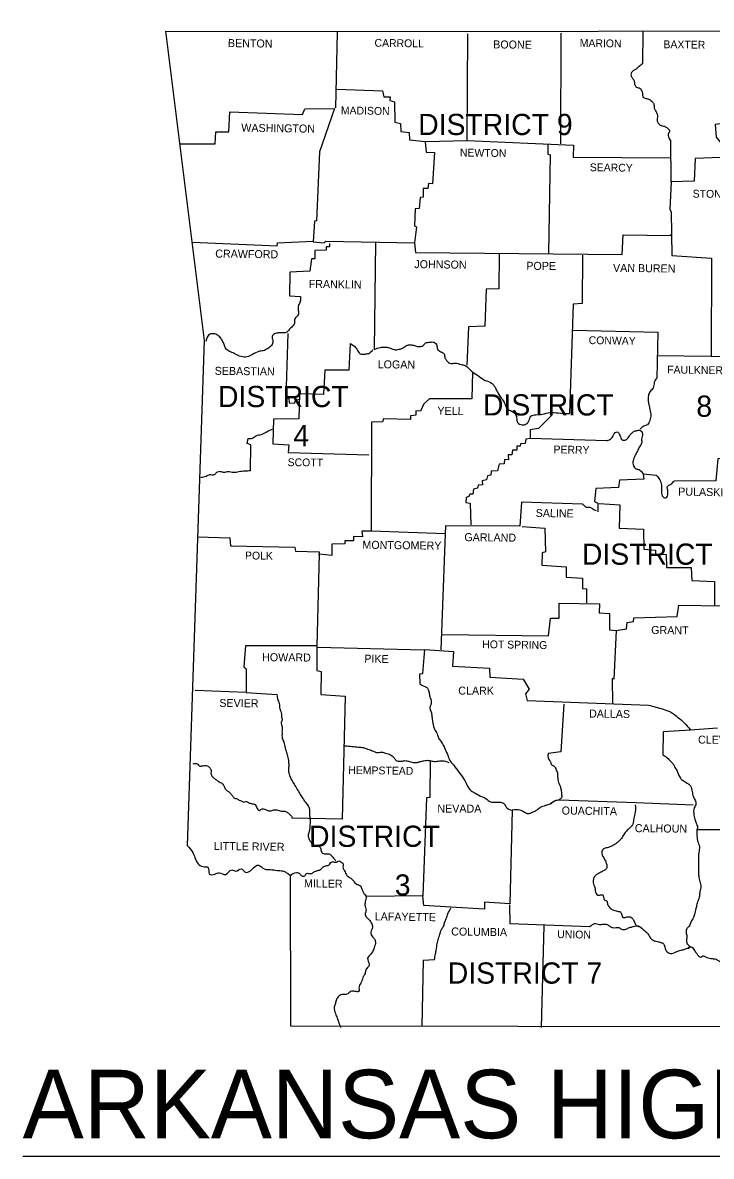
# Model space of a CAD drawing. Extents: x -42408 to 34530, y -43140 to 20491.
# Drawn here: x 7249 to 9102, y 6993 to 10043 of the extents above; entities that cross this region are included whole.
import ezdxf

# ---------------------------------------------------------------- set-up
doc = ezdxf.new("R2010")
doc.units = 0
for name, color, linetype in [('1', 7, 'Continuous'), ('2', 7, 'Continuous'), ('3', 7, 'Continuous')]:
    doc.layers.add(name, color=color, linetype=linetype)

msp = doc.modelspace()

# ---------------------------------------------------------------- linework, layer by layer
at = {"layer": '1'}
for points in [[(7633.7, 10020), (8443.3, 10019.5), (9153.8, 10021), (9991.9, 10034), (10380.4, 10043)], [(7633.7, 10020), (7737.4, 9187.8), (7692.3, 7829.5)], [(8095.9, 10017), (8091.3, 9814.2)], [(8094.9, 9863.7), (8218, 9859.7), (8221, 9843.7), (8238, 9843.2), (8237.5, 9833.2), (8249.6, 9830.2), (8250.6, 9775.6), (8266.1, 9772.1), (8267.1, 9750.6), (8289.1, 9747.6), (8290.1, 9727.6), (8333.7, 9723.1), (8445.8, 9725.6), (8446.8, 10013.4)], [(8697.7, 10014.5), (8696.2, 9717.1)], [(8918, 10018), (8917, 9932.3)], [(9153.8, 10018), (9154.8, 9898.8), (9146.3, 9898.3), (9147.8, 9773.6), (9112.7, 9768.6), (9115.7, 9735.1), (9127.7, 9719.6), (9126.7, 9680), (9058.6, 9677.5), (9056.1, 9616.4), (8994.1, 9614.4), (8991, 9540.3), (8994.6, 9534.3), (8996.1, 9416.2), (9103.2, 9409.1), (9101.7, 9145.3), (9186.8, 9142.8), (9186.8, 8874.4), (9119.7, 8869.4), (9114.7, 8810.3), (9002.1, 8809.8)], [(7673.3, 9717.1), (7766.9, 9716.6), (7769.4, 9749.6), (7804, 9749.6), (7807, 9803.2), (8002.2, 9796.2), (8008.2, 9811.2), (8088.8, 9811.7), (8048.3, 9695.5), (8040.3, 9509.8), (8034.3, 9509.3), (8031.3, 9453.2), (8060.8, 9450.7), (8065.3, 9455.2), (8304.1, 9450.7), (8306.6, 9424.2)], [(8332.7, 9722.1), (8334.7, 9695), (8357.7, 9693.5), (8351.7, 9609.4), (8341.2, 9609.9), (8339.2, 9596.4), (8327.2, 9596.4), (8326.7, 9573.4), (8319.2, 9572.9), (8316.6, 9543.3), (8305.6, 9541.8), (8304.1, 9496.8), (8309.1, 9493.3), (8304.1, 9450.7)], [(8445.8, 9725.6), (8731.2, 9713.5), (8730.7, 9681), (8992.6, 9679)], [(8662.6, 9715.1), (8662.1, 9689), (8668.6, 9687.5), (8664.6, 9423.2)], [(8994.1, 9614.4), (8993.6, 9727.1)], [(8306.6, 9424.2), (8862.4, 9419.7), (8864.9, 9472.2), (8994.1, 9470.7)], [(8992.6, 9471.2), (8994.1, 9472.7)], [(7706.3, 9452.7), (7934.1, 9442.2), (7935.1, 9450.2), (8030.3, 9454.7)], [(8075.3, 9448.7), (8075.3, 9439.7), (8065.8, 9439.7), (8066.3, 9430.7), (8035.8, 9430.2), (8035.3, 9407.6), (8026.8, 9407.6), (8022.3, 9374.1), (7968.2, 9371.6), (7967.7, 9308), (7996.7, 9306)], [(8199, 9452.7), (8195.5, 9163.8)], [(8531.4, 9420.2), (8530.9, 9326.5), (8496.4, 9326), (8493.4, 9226.4), (8449.3, 9224.9), (8444.3, 9121.8)], [(8755.7, 9417.7), (8754.7, 9287.5), (8730.7, 9285.5), (8721.2, 8991.1)], [(8729.7, 9215.9), (8958.5, 9210.4), (8955.5, 9086.7)], [(7962.7, 9206.9), (7957.7, 9034.6), (7965.2, 9032.6), (7966.7, 9020.6), (7981.7, 9019.6), (7983.2, 9028.1), (7995.2, 9030.1)], [(8130.9, 9179.8), (8127.4, 9108.2), (8062.3, 9107.7), (8058.8, 9042.7), (7994.2, 9044.2), (7992.2, 8977.1), (7924.6, 8976.6), (7922.6, 8909.5), (7965.2, 8907), (7963.7, 8886.4), (8181, 8880.4)], [(8956, 9147.3), (9101.7, 9145.3)], [(8459.8, 9103.2), (8457.8, 9031.1), (8343.7, 9030.6), (8328.7, 9017.6), (8320.2, 8997.6), (8307.6, 8998.6), (8307.1, 8987.1), (8292.6, 8985.6), (8293.1, 8975.1), (8220.5, 8977.1), (8218, 8969.1), (8188, 8968.1), (8187, 8675.2), (8161.9, 8674.7), (8163.9, 8659.6), (8139.9, 8660.1), (8139.4, 8649.1), (8115.9, 8649.1), (8116.4, 8641.1), (8081.3, 8640.1), (8080.8, 8609.6), (8046.8, 8612.6), (8041.3, 8366.3), (7848.5, 8366.8), (7844, 8309.7), (7851, 8304.7), (7850.5, 8240.6), (7713.8, 8246.6)], [(8674.6, 8989.1), (8656.6, 8969.6), (8637.1, 8951), (8614.5, 8947.5), (8614.5, 8924), (8603.5, 8922.5), (8601.5, 8910.5), (8589, 8909.5), (8588, 8904), (8579.5, 8903.5), (8579, 8893), (8567, 8892.5), (8566, 8880.4), (8556, 8880.4), (8556.5, 8866.4), (8545.5, 8867.4), (8545, 8856.4), (8531.4, 8855.4), (8527.4, 8837.4), (8510.4, 8835.9), (8508.9, 8825.9), (8499.9, 8823.4), (8497.4, 8812.8), (8485.9, 8810.3), (8486.9, 8799.8), (8475.4, 8798.8), (8473.4, 8790.8), (8462.8, 8787.8), (8460.3, 8774.3), (8452.3, 8774.8), (8449.8, 8767.8), (8442.3, 8765.3), (8441.8, 8751.8), (8453.3, 8749.8), (8455.3, 8691.7)], [(7862, 8836.9), (7863.5, 8907.5), (7853.5, 8910.5), (7856.5, 8924)], [(8821.3, 8918), (8615, 8924.5)], [(8955, 8824.4), (8919, 8828.4), (8920.5, 8814.9), (8854.9, 8812.3), (8852.9, 8792.8), (8791.3, 8789.3), (8787.8, 8754.3), (8796.8, 8749.8), (8796.8, 8726.7)], [(8755.7, 8747.8), (8592, 8752.8), (8587.5, 8688.2), (8387.2, 8689.2), (8386.2, 8667.7)], [(8800.3, 8749.3), (8856.4, 8745.8), (8854.4, 8683.2), (8920, 8680.7), (8921, 8626.1), (8952, 8623.6), (8952, 8614.1), (8981, 8612.1), (8982, 8577), (9048.1, 8577), (9050.1, 8542.5), (9111.2, 8539.5), (9110.7, 8474.4)], [(8386.2, 8667.7), (8187, 8675.2)], [(8386.2, 8667.7), (8374.7, 8355.7)], [(8593.5, 8687.2), (8654.1, 8682.7), (8656.1, 8619.6), (8647.6, 8616.6), (8646.6, 8583), (8712.2, 8578.5), (8712.2, 8551), (8755.7, 8548.5), (8756.2, 8521), (8766.7, 8519.5), (8766.2, 8482.4)], [(7719.9, 8659.6), (7806.5, 8656.6), (7808.5, 8635.6), (7981.7, 8632.1), (7983.7, 8621.1), (8046.8, 8619.1), (8046.3, 8609.6)], [(8378.2, 8397.3), (8664.6, 8393.3), (8670.1, 8440.9), (8692.7, 8440.9), (8693.2, 8480.9), (8801.3, 8479.4), (8800.3, 8455.4), (8828.3, 8453.4), (8828.3, 8409.3), (8846.4, 8407.8)], [(8846.4, 8407.8), (8874.4, 8411.8), (8876.4, 8428.8), (8892.9, 8431.8), (8893.9, 8441.9), (9010.6, 8445.4), (9015.1, 8475.9), (9134.7, 8473.9)], [(8846.4, 8407.8), (8840.3, 8276.6), (8835.8, 8278.1), (8836.3, 8210)], [(8041.3, 8366.3), (8041.3, 8299.7), (8052.3, 8297.7), (8051.3, 8235.6), (8117.4, 8230.6), (8109.4, 7899.6), (7973.2, 7903.1)], [(8042.3, 8362.7), (8328.7, 8355.2)], [(8319.2, 8263.6), (8318.2, 8291.2), (8326.2, 8291.7), (8331.2, 8356.2), (8408.3, 8351.2), (8406.3, 8311.7), (8505.9, 8306.2), (8506.4, 8282.1), (8596.5, 8276.6), (8612, 8249.6), (8602.5, 8237.6), (8607, 8219.1), (8933.5, 8207)], [(7850.5, 8240.6), (7933.6, 8235.6)], [(8705.2, 8209.5), (8697.7, 8080.9), (8663.1, 8076.9)], [(9118.7, 8144.5), (9045.6, 8139.9)], [(9046.6, 8139.9), (8972.5, 8135.4), (8972, 8072.9)], [(8345.7, 8057.8), (8344.7, 7958.2), (8335.7, 7957.2), (8325.7, 7693.4)], [(8692.7, 7952.2), (8899.9, 7944.7), (9053.6, 7938.7)], [(8566.5, 7924.2), (8560, 7671.8), (8492.4, 7676.3), (8491.9, 7657.8), (8401.8, 7663.3)], [(9063.6, 7872.1), (9289.9, 7872.6)], [(7969.2, 7748.9), (7970.2, 7343.9), (9805.1, 7340.9)], [(8401.8, 7663.3), (8329.2, 7667.3), (8325.7, 7693.4), (8174, 7691.9)], [(8774.8, 7610.7), (8561, 7618.8), (8560, 7669.3)], [(8652.1, 7614.2), (8644.1, 7339.4)], [(8357.7, 7521.6), (8326.7, 7519.6), (8323.2, 7343.4)]]:
    msp.add_lwpolyline(points, dxfattribs=at)
for points in [[(8917, 9932.3), (8907.9, 9924.8), (8899.9, 9917.8), (8887.9, 9909.3), (8886.4, 9901.3), (8890.4, 9893.3), (8894.4, 9886.8), (8895.9, 9877.8), (8899.4, 9870.3), (8907.9, 9867.3), (8914.9, 9860.7), (8917.5, 9851.7), (8918.5, 9843.2), (8926.5, 9839.2), (8935.5, 9836.2), (8944, 9830.2), (8948, 9822.7), (8949, 9813.2), (8952.5, 9805.7), (8956.5, 9796.7), (8957.5, 9789.1), (8956.5, 9781.6), (8958.5, 9774.6), (8965, 9767.6), (8976.5, 9764.1), (8984.5, 9759.1), (8990, 9752.1), (8986.5, 9743.6), (8987, 9736.1), (8991.5, 9727.1)], [(7996.7, 9306), (7996.7, 9295.5), (7992.7, 9284.5), (7990.2, 9275), (7991.7, 9262.4), (7987.2, 9252.4), (7980.7, 9244.4), (7980.7, 9234.4), (7973.2, 9223.9), (7965.2, 9215.9), (7958.2, 9209.4), (7945.7, 9208.4), (7935.1, 9207.9), (7924.6, 9204.4), (7920.6, 9196.9), (7922.6, 9185.3), (7918.6, 9174.3), (7908.1, 9165.8), (7896.6, 9160.3), (7884.6, 9158.3), (7868.1, 9150.3), (7853, 9143.8), (7837, 9144.8), (7822, 9151.3), (7808.5, 9157.3), (7798, 9163.3), (7789.4, 9181.8), (7783.9, 9191.9), (7774.4, 9201.9), (7762.9, 9205.9), (7753.4, 9204.9), (7741.9, 9185.3)], [(8195.5, 9163.8), (8212, 9169.3), (8224, 9170.3), (8236, 9168.3), (8248.6, 9163.3), (8262.1, 9164.3), (8272.1, 9167.8), (8282.1, 9174.3), (8293.1, 9176.3), (8303.6, 9174.3), (8314.6, 9171.3), (8326.7, 9174.8), (8333.7, 9181.3), (8345.7, 9183.3), (8356.2, 9183.3), (8363.7, 9174.8), (8365.2, 9165.8), (8374.7, 9157.3), (8383.2, 9151.8), (8385.7, 9141.3), (8390.2, 9133.8), (8394.8, 9128.8), (8401.3, 9125.8), (8412.3, 9126.8), (8429.3, 9123.3), (8440.3, 9120.8), (8450.3, 9112.2), (8459.8, 9103.2)], [(8130.9, 9179.8), (8141.9, 9172.8), (8150.4, 9161.3), (8157.9, 9151.8), (8170.5, 9151.3), (8180.5, 9153.3), (8192, 9163.3)], [(8459.8, 9103.2), (8477.4, 9091.2), (8493.9, 9080.7), (8510.9, 9073.2), (8520.4, 9062.2), (8528.9, 9045.2), (8535.9, 9034.6), (8545, 9021.6), (8551.5, 9007.1), (8562, 8999.1), (8573, 8992.1), (8578.5, 8979.6), (8581, 8967.1), (8593, 8961), (8604.5, 8963.5), (8611, 8971.1), (8617.1, 8984.1), (8630.6, 8988.1), (8648.1, 8989.6), (8668.1, 8994.1), (8690.1, 8993.1), (8721.2, 8991.1)], [(8955.5, 9086.7), (8949, 9075.2), (8946, 9060.2), (8938, 9050.7), (8933, 9039.6), (8932.5, 9025.1), (8935, 9012.1), (8937.5, 8999.6), (8939.5, 8988.1), (8937, 8973.6), (8930.5, 8961), (8920.5, 8957.5), (8910.9, 8949)], [(7856.5, 8924), (7867.6, 8925), (7878.1, 8932), (7892.1, 8935), (7906.1, 8942.5), (7923.6, 8950.5)], [(8821.3, 8918), (8833.8, 8925), (8840.3, 8935.5), (8848.4, 8942), (8856.4, 8933), (8863.4, 8920), (8870.9, 8920), (8880.4, 8929), (8886.4, 8937), (8893.9, 8943), (8901.9, 8945.5), (8910.4, 8946.5), (8917, 8937), (8914.9, 8922), (8914.9, 8912), (8909.4, 8901.5), (8903.4, 8890.5), (8896.9, 8877.9), (8891.9, 8864.4), (8892.9, 8851.4), (8899.9, 8842.9), (8907.9, 8840.4), (8919, 8829.4)], [(7862, 8836.9), (7847.5, 8836.4), (7831, 8834.4), (7816, 8832.4), (7802.5, 8834.9), (7789.9, 8832.9), (7781.4, 8834.9), (7770.9, 8832.4), (7764.9, 8826.4), (7752.4, 8826.4), (7743.4, 8822.4), (7728.9, 8818.9)], [(8955, 8824.4), (8963.5, 8813.3), (8968.5, 8798.3), (8968.5, 8781.3), (8972.5, 8767.3), (8980.5, 8764.3), (8985.5, 8776.3), (8984.5, 8788.3), (8984.5, 8795.3), (8993.1, 8801.3), (9002.1, 8809.8)], [(8793.3, 8729.2), (8783.8, 8734.2), (8776.3, 8738.7), (8768.3, 8738.2), (8761.7, 8742.3), (8755.7, 8747.8)], [(7933.6, 8235.6), (7936.1, 8220.6), (7940.6, 8207.5), (7941.1, 8197.5), (7945.7, 8182.5), (7945.7, 8177), (7947.2, 8166), (7945.2, 8160), (7947.7, 8148), (7947.2, 8138.9), (7947.2, 8131.4), (7947.7, 8118.9), (7951.7, 8107.9), (7955.7, 8091.4), (7958.2, 8082.9), (7962.2, 8069.9), (7964.7, 8053.8), (7965.2, 8041.8), (7964.2, 8030.8), (7967.2, 8018.3), (7972.7, 8005.8), (7979.7, 7993.8), (7988.2, 7980.2), (7994.2, 7969.7), (8001.7, 7958.2), (8007.7, 7948.7), (8016.7, 7936.7), (8020.8, 7926.7), (8020.8, 7912.6), (8022.8, 7899.6), (8022.3, 7885.1), (8021.3, 7872.1), (8017.8, 7854.1), (8020.3, 7845.6), (8029.8, 7833), (8035.8, 7829.5), (8046.3, 7827.5), (8051.3, 7820.5), (8054.3, 7810), (8064.8, 7806.5), (8076.3, 7805.5), (8081.8, 7799.5), (8089.3, 7791.5), (8091.8, 7787.5)], [(8319.2, 8263.6), (8327.2, 8258.6), (8336.7, 8254.1), (8341.7, 8246.6), (8343.7, 8235.1), (8347.2, 8222.6), (8348.2, 8209.5), (8345.2, 8202.5), (8349.2, 8186.5), (8350.7, 8175.5), (8352.2, 8162.5), (8356.2, 8145), (8362.7, 8132.9), (8368.7, 8118.4), (8378.7, 8102.9), (8387.2, 8085.9), (8391.2, 8076.9), (8398.8, 8058.3), (8408.3, 8045.8), (8423.3, 8026.8), (8436.8, 8007.3), (8444.3, 7992.8), (8455.8, 7976.7), (8468.9, 7968.7), (8485.4, 7960.2), (8495.9, 7955.2), (8507.9, 7946.7), (8523.4, 7945.7), (8534.9, 7945.7), (8545.5, 7941.2), (8550.5, 7932.2), (8559.5, 7926.2), (8566.5, 7924.2)], [(8933.5, 8207), (8972.5, 8196), (8992.6, 8188.5), (9012.6, 8174), (9029.1, 8159.5), (9045.6, 8141)], [(8116.4, 8097.4), (8135.4, 8095.9), (8152.9, 8093.9), (8166.4, 8092.4), (8180.5, 8087.4), (8193, 8082.9), (8201, 8079.4), (8214.5, 8080.4), (8226, 8077.9), (8239, 8073.4), (8248.6, 8064.8), (8254.6, 8058.3), (8266.1, 8055.8), (8275.6, 8057.3), (8287.1, 8056.3), (8300.1, 8052.3), (8310.6, 8052.8), (8319.2, 8054.8), (8329.2, 8057.3), (8341.7, 8058.3), (8351.2, 8056.3), (8363.7, 8055.8), (8378.2, 8057.3), (8396.3, 8052.3)], [(8663.1, 8076.9), (8663.1, 8067.4), (8666.6, 8058.3), (8670.1, 8054.3), (8671.6, 8047.8), (8676.1, 8044.8), (8682.6, 8038.8), (8686.1, 8030.3), (8688.6, 8024.8), (8688.6, 8017.8), (8689.1, 8010.8), (8690.1, 8002.3), (8696.2, 7987.2), (8697.7, 7981.2), (8698.7, 7976.2), (8699.2, 7967.7), (8699.2, 7957.7), (8692.7, 7952.2)], [(8972, 8072.9), (8983.5, 8065.4), (8993.1, 8055.3), (9000.1, 8047.8), (9004.6, 8039.3), (9010.6, 8029.3), (9019.1, 8010.3), (9026.6, 8003.8), (9037.1, 7997.3), (9043.6, 7992.8), (9050.1, 7978.2), (9053.1, 7963.7), (9058.6, 7950.7), (9061.1, 7940.7), (9056.6, 7930.7), (9055.6, 7910.6), (9058.6, 7897.1), (9062.6, 7887.1), (9065.1, 7875.6), (9063.6, 7872.1)], [(7707.8, 8048.8), (7718.9, 8049.3), (7726.4, 8042.8), (7730.9, 8043.3), (7738.9, 8044.3), (7746.4, 8043.8), (7751.9, 8039.3), (7756.4, 8031.3), (7755.9, 8023.8), (7756.4, 8020.8), (7759.9, 8014.3), (7765.9, 8009.3), (7772.4, 8004.3), (7778.4, 8000.3), (7788.4, 7993.8), (7789.4, 7991.8), (7793.5, 7983.7), (7798.5, 7977.2), (7804.5, 7973.2), (7811, 7966.2), (7814, 7963.2), (7819, 7956.2), (7824.5, 7955.7), (7832, 7951.2), (7837.5, 7949.7), (7843.5, 7945.7), (7849.5, 7947.7), (7857, 7944.7), (7867, 7941.7), (7872.6, 7940.7), (7879.1, 7931.2), (7885.6, 7923.2), (7893.6, 7927.7), (7908.6, 7923.2), (7918.1, 7922.7), (7926.6, 7925.2), (7933.1, 7924.7), (7945.2, 7921.7), (7952.7, 7921.7), (7960.7, 7918.7), (7968.2, 7912.6), (7973.2, 7906.1), (7973.2, 7903.1)], [(8683.1, 7950.2), (8670.1, 7941.7), (8660.1, 7937.7), (8652.6, 7935.2), (8645.6, 7933.2), (8636.6, 7927.2), (8629.6, 7922.2), (8620.1, 7917.7), (8611, 7914.6), (8600, 7918.2), (8594, 7921.7), (8587.5, 7924.2), (8566.5, 7924.2)], [(8670.1, 7941.7), (8683.1, 7950.2), (8692.7, 7952.2)], [(8897.9, 7938.7), (8896.9, 7913.6), (8893.4, 7898.1), (8889.9, 7884.1), (8882.4, 7876.1), (8874.4, 7868.1), (8866.9, 7859.1), (8860.4, 7848.1), (8853.9, 7841.1), (8845.4, 7834), (8836.8, 7829), (8827.3, 7824.5), (8816.8, 7822), (8809.3, 7816.5), (8808.8, 7804.5), (8817.3, 7787.5), (8820.3, 7779.5), (8821.3, 7770), (8817.8, 7764.4), (8809.8, 7759.9), (8800.3, 7754.4), (8791.8, 7749.4), (8785.8, 7740.9), (8784.8, 7729.4), (8788.8, 7715.9), (8790.3, 7707.9), (8796.8, 7695.4), (8801.8, 7695.9), (8810.8, 7695.4), (8811.8, 7692.9), (8812.3, 7690.3), (8814.3, 7683.8), (8821.8, 7678.3), (8822.8, 7673.3), (8827.3, 7663.8), (8834.8, 7657.3), (8840.3, 7655.3), (8851.9, 7651.8), (8857.9, 7650.3), (8864.4, 7635.8), (8872.4, 7636.3), (8878.4, 7637.3), (8888.4, 7634.8), (8892.9, 7628.8), (8897.4, 7618.8), (8903.4, 7611.7), (8907.4, 7611.7)], [(9063.6, 7872.1), (9065.6, 7841.1), (9070.2, 7826), (9068.7, 7810), (9068.2, 7794.5), (9068.2, 7780.5), (9068.2, 7767), (9068.2, 7752.9), (9069.2, 7742.9), (9072.7, 7728.4), (9074.2, 7714.9), (9071.2, 7701.9), (9069.7, 7689.8), (9065.6, 7677.8), (9062.1, 7664.3), (9058.1, 7646.8), (9054.6, 7635.3), (9047.6, 7623.3), (9043.1, 7612.2), (9036.1, 7605.2), (9035.1, 7593.2), (9036.6, 7582.2), (9035.6, 7572.2), (9039.1, 7562.7), (9048.1, 7556.2)], [(7692.3, 7829.5), (7706.8, 7810.5), (7712.8, 7797), (7721.4, 7779.5), (7733.9, 7772.5), (7748.4, 7770), (7751.4, 7752.9), (7766.4, 7752.4), (7778.4, 7755.9), (7795, 7751.4), (7812.5, 7763.4), (7822.5, 7760.4), (7837, 7766.5), (7848, 7757.4), (7867, 7765.5), (7884.1, 7776.5), (7900.1, 7766), (7915.6, 7764.4), (7934.1, 7761.9), (7948.7, 7760.9), (7961.7, 7754.4), (7971.2, 7747.9), (7969.2, 7748.9)], [(7969.2, 7748.9), (7986.7, 7756.4), (7994.2, 7753.9), (8000.7, 7747.4), (8008.2, 7747.4), (8012.2, 7753.4), (8019.8, 7753.9), (8025.8, 7753.4), (8032.3, 7757.4), (8037.8, 7759.9), (8045.3, 7762.4), (8050.8, 7764.4), (8055.8, 7770), (8064.8, 7774.5), (8075.3, 7778), (8078.3, 7783), (8083.3, 7785), (8093.4, 7784.5), (8099.9, 7787.5), (8105.4, 7785), (8110.4, 7781.5), (8111.4, 7768.5), (8115.4, 7761.4), (8121.4, 7748.9), (8129.9, 7742.4), (8137.9, 7735.9), (8140.9, 7731.9), (8149.4, 7724.4), (8156.9, 7721.9), (8160.4, 7716.4), (8165.9, 7703.4), (8174, 7691.9)], [(8174, 7691.9), (8171, 7677.3), (8170.5, 7665.8), (8173, 7652.3), (8170.5, 7645.8), (8174.5, 7636.3), (8182, 7628.8), (8187.5, 7620.8), (8191, 7609.2), (8186.5, 7596.2), (8191.5, 7582.7), (8196, 7577.7), (8198.5, 7569.7), (8195, 7554.2), (8190.5, 7542.7), (8180.5, 7531.1), (8177.5, 7525.6), (8179, 7518.1), (8181.5, 7506.1), (8179, 7502.6), (8172.5, 7494.1), (8170.5, 7484.6), (8165.9, 7476.6), (8160.9, 7462), (8154.4, 7450), (8153.4, 7436.5), (8143.4, 7436.5), (8131.9, 7436.5), (8121.4, 7429), (8111.9, 7428.5), (8100.4, 7424), (8093.4, 7414.5), (8090.8, 7404), (8087.8, 7394), (8090.8, 7376.9), (8095.4, 7364.9), (8098.9, 7355.4), (8104.9, 7339.9)], [(8357.7, 7521.6), (8360.2, 7537.6), (8362.7, 7550.2), (8364.2, 7562.2), (8367.2, 7575.7), (8371.7, 7590.2), (8375.7, 7602.2), (8381.2, 7610.7), (8384.7, 7620.8), (8389.2, 7632.8), (8393.8, 7645.3), (8401.8, 7661.3)], [(8774.8, 7610.7), (8782.8, 7616.3), (8790.3, 7619.3), (8797.8, 7617.8), (8805.8, 7616.8), (8812.8, 7617.8), (8821.8, 7616.3), (8829.3, 7611.7), (8837.8, 7608.2), (8846.4, 7608.2), (8853.9, 7608.2), (8860.4, 7603.7), (8872.4, 7604.2), (8882.4, 7608.2), (8892.4, 7611.2), (8905.9, 7612.7), (8918, 7604.2), (8926.5, 7597.2), (8933.5, 7589.2), (8938.5, 7580.2), (8944, 7575.2), (8953, 7571.7), (8960, 7570.2), (8968.5, 7567.7), (8973, 7565.7), (8977, 7556.2), (8983.5, 7543.2), (8996.1, 7538.6), (9011.6, 7544.7), (9024.1, 7548.2), (9033.1, 7551.2), (9038.6, 7553.2), (9043.6, 7553.7), (9042.1, 7554.7), (9048.1, 7556.2), (9053.6, 7552.2), (9057.1, 7546.7), (9063.1, 7538.6), (9068.7, 7531.6), (9074.2, 7529.1), (9079.7, 7532.1), (9087.2, 7529.6), (9093.7, 7527.1), (9101.2, 7525.1), (9107.7, 7524.6), (9116.2, 7522.6), (9122.7, 7519.1), (9128.7, 7515.6), (9134.7, 7509.1), (9140.7, 7499.1), (9142.8, 7491.1), (9149.8, 7483.1), (9156.3, 7483.1), (9165.8, 7470.1), (9169.3, 7465), (9176.8, 7456), (9182.3, 7456), (9192.8, 7454)]]:
    msp.add_spline(points, degree=3, dxfattribs=at)
at = {"layer": '2'}
msp.add_line((7249.3, 6992.9), (10598.6, 6992.9), dxfattribs=at)

# ---------------------------------------------------------------- texts
for s, height, rotation, p in [('BENTON', 21.53, 359.2527, (7801.5, 9977.4)), ('CARROLL', 21.03, 359.1481, (8196, 9978.4)), ('BOONE', 21.53, 359.4001, (8515.4, 9973.9)), ('MARION', 21.03, 359.1854, (8748.2, 9977.9)), ('BAXTER', 21.03, 359.2559, (8973.5, 9974.4)), ('MADISON', 21.03, 359.0906, (8105.4, 9796.7)), ('WASHINGTON', 21.52, 359.232, (7837.5, 9749.6)), ('NEWTON', 21.03, 359.2717, (8425.8, 9683)), ('SEARCY', 21.02, 359.2527, (8775.3, 9643.5)), ('STONE', 21.02, 359.4001, (9052.1, 9572.4)), ('CRAWFORD', 21.52, 359.2771, (7767.4, 9411.1)), ('JOHNSON', 21.53, 359.3514, (8303.1, 9382.6)), ('POPE', 21.53, 359.6155, (8604.5, 9378.1)), ('VAN BUREN', 21.53, 359.3508, (8837.8, 9372.6)), ('FRANKLIN', 21.53, 359.1815, (8018.8, 9329.5)), ('CONWAY', 21.02, 359.0371, (8772.3, 9178.3)), ('LOGAN', 21.53, 359.3969, (8204.5, 9113.2)), ('FAULKNER', 21.03, 359.2486, (8983.5, 9099.2)), ('SEBASTIAN', 21.52, 359.2816, (7765.9, 9095.7)), ('YELL', 21.53, 359.1987, (8365.2, 8988.1)), ('PERRY', 21.03, 359.0858, (8677.6, 8884.4)), ('SCOTT', 21.03, 359.4063, (7962.2, 8849.9)), ('PULASKI', 21.53, 359.053, (9013.1, 8770.8)), ('SALINE', 21.53, 359.1491, (8629.6, 8713.2)), ('GARLAND', 21.53, 359.3658, (8437.8, 8648.1)), ('MONTGOMERY', 21.53, 359.2944, (8163.4, 8627.6)), ('POLK', 21.02, 359.2152, (7847.5, 8599.1)), ('GRANT', 21.53, 359.4032, (8940.5, 8398.3)), ('HOT SPRING', 21.03, 359.2216, (8485.9, 8360.2)), ('HOWARD', 21.53, 359.5145, (7893.6, 8325.2)), ('PIKE', 21.52, 359.0452, (8168.5, 8321.2)), ('SEVIER', 21.53, 359.4271, (7778.4, 8202)), ('DALLAS', 21.52, 359.2462, (8773.3, 8173.5)), ('CLEVELAND', 21.53, 359.3377, (9066.6, 8103.4)), ('HEMPSTEAD', 21.02, 359.1885, (8125.4, 8021.8)), ('OUACHITA', 21.53, 359.2043, (8699.7, 7912.6)), ('CALHOUN', 21.53, 359.3634, (8896.4, 7865.1)), ('LITTLE RIVER', 21.53, 359.1697, (7763.4, 7817.5)), ('MILLER', 21.52, 359.1319, (8006.2, 7716.9)), ('LAFAYETTE', 21.52, 359.1839, (8196.5, 7627.8)), ('COLUMBIA', 21.52, 359.2125, (8402.3, 7587.2)), ('UNION', 21.03, 358.9584, (8687.6, 7580.2))]:
    msp.add_text(s, height=height, rotation=rotation, dxfattribs=at).set_placement(p)
for s, height, p in [('CLARK', 21.53, (8421.4, 8235)), ('NEVADA', 21.53, (8365.2, 7917.7)), ('ARKANSAS HIGHWAY DISTRICT 2', 184.218, (7249.3, 7041.5))]:
    msp.add_text(s, height=height, dxfattribs=at).set_placement(p)
at = {"layer": '3'}
for s, height, p in [('DISTRICT 9', 57.08, (8313.6, 9740.6)), ('DISTRICT', 57.08, (7774.9, 9008.6)), ('DISTRICT', 57.08, (8487.9, 8986.1)), ('8', 57.1, (9062.1, 8982.6)), ('4', 57.1, (7977.7, 8903.5)), ('DISTRICT 6', 57.08, (8754.2, 8584.5)), ('DISTRICT', 57.08, (8020, 7825.5)), ('3', 56.6, (8250.8, 7694.8)), ('DISTRICT 7', 57.08, (8393.3, 7457.5))]:
    msp.add_text(s, height=height, dxfattribs=at).set_placement(p)

doc.saveas('drawing.dxf')
